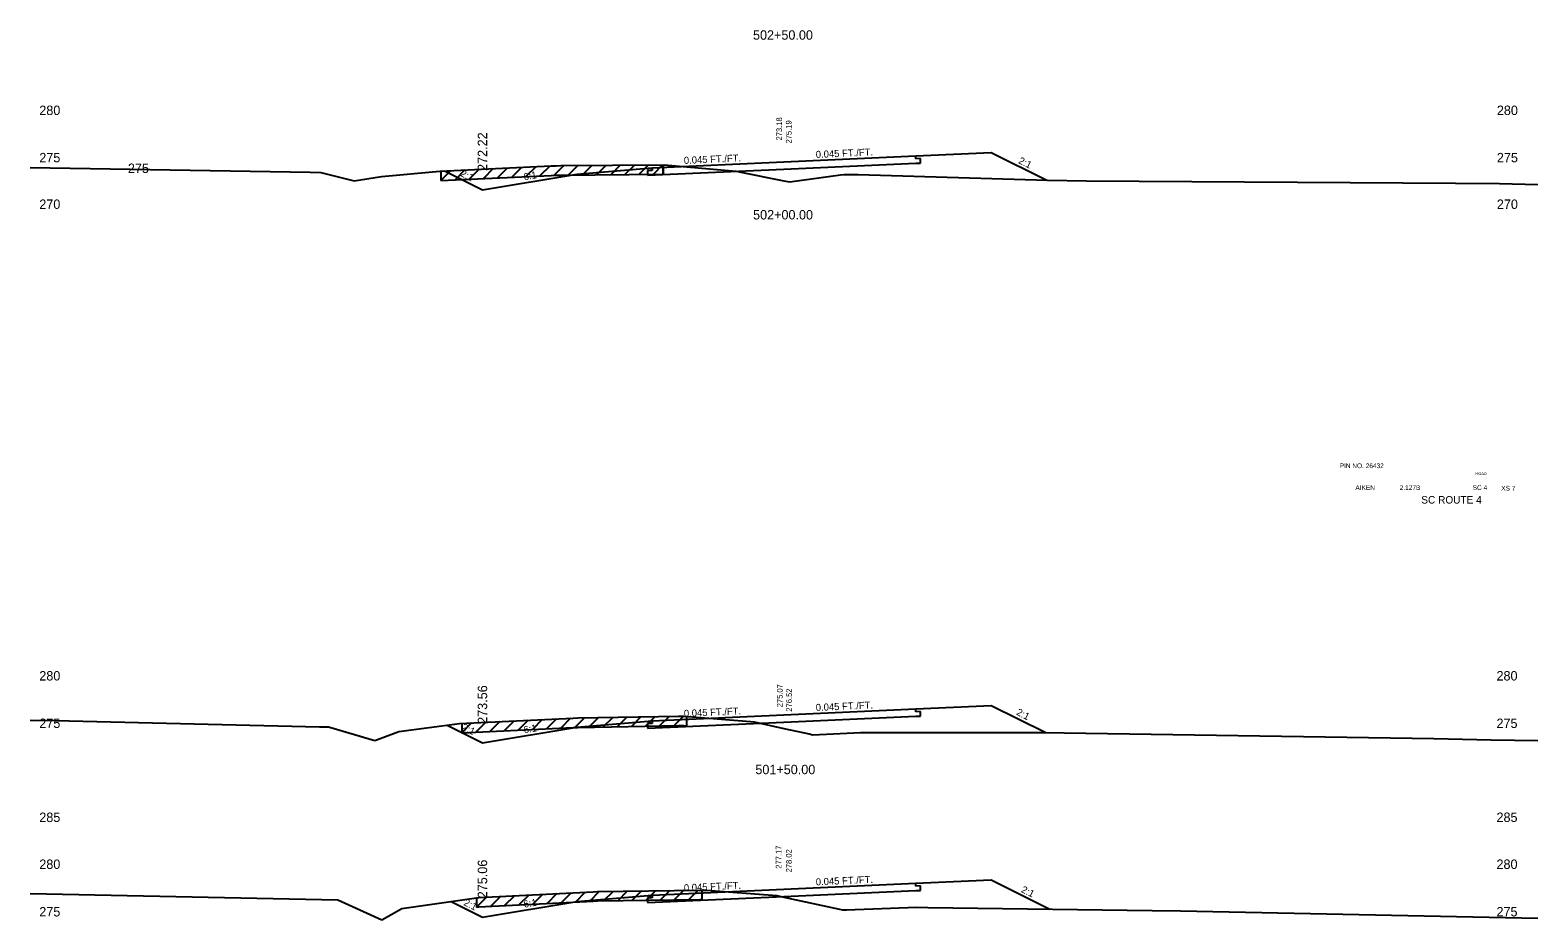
# Model space of a CAD drawing. Extents: x 883 to 1160, y 1002 to 4323.
# Drawn here: x 1000 to 1160, y 1744.8 to 1839.2 of the extents above; entities that cross this region are included whole.
import ezdxf

# ---------------------------------------------------------------- set-up
doc = ezdxf.new("R2010")
doc.units = 0
for name, color, linetype in [('Level 1', 7, 'Continuous'), ('Level 10', 7, 'Continuous'), ('Level 11', 7, 'Continuous'), ('Level 12', 7, 'Continuous'), ('Level 3', 7, 'Continuous'), ('Level 32', 7, 'Continuous'), ('Level 33', 7, 'Continuous'), ('Level 59', 7, 'Continuous'), ('Level 6', 7, 'Continuous'), ('Level 60', 7, 'Continuous'), ('Level 61', 7, 'Continuous'), ('Level 7', 7, 'Continuous')]:
    doc.layers.add(name, color=color, linetype=linetype)

msp = doc.modelspace()

# ---------------------------------------------------------------- linework, layer by layer
at = {"layer": 'Level 11'}
for p, q in [((1094, 1825.52), (1094, 1825.82)), ((1094.5, 1825.54), (1094, 1825.52)), ((1094, 1825.04), (1094.5, 1825.06)), ((1094.5, 1825.06), (1094.5, 1825.54)), ((1094, 1766.85), (1094, 1767.15)), ((1094.5, 1766.87), (1094, 1766.85)), ((1094.5, 1766.39), (1094.5, 1766.87)), ((1094, 1766.37), (1094.5, 1766.39)), ((1094, 1748.35), (1094, 1748.65)), ((1094.5, 1748.37), (1094, 1748.35)), ((1094, 1747.87), (1094.5, 1747.89)), ((1094.5, 1747.89), (1094.5, 1748.37))]:
    msp.add_line(p, q, dxfattribs=at)
at = {"layer": 'Level 12'}
for p, q in [((1065.5, 1823.78), (1080, 1824.41)), ((1066, 1824.26), (1065.5, 1824.26)), ((1065.5, 1824.26), (1065.5, 1823.78)), ((1066, 1824.56), (1066, 1824.26)), ((1067.19, 1824.86), (1067.19, 1823.83)), ((1080, 1824.41), (1094, 1825.04)), ((1065.5, 1765.11), (1080, 1765.74)), ((1066, 1765.59), (1065.5, 1765.59)), ((1065.5, 1765.59), (1065.5, 1765.11)), ((1066, 1765.89), (1066, 1765.59)), ((1080, 1765.74), (1094, 1766.37)), ((1065.5, 1746.61), (1080, 1747.24)), ((1066, 1747.39), (1066, 1747.09)), ((1080, 1747.24), (1094, 1747.87)), ((1066, 1747.09), (1065.5, 1747.09)), ((1065.5, 1747.09), (1065.5, 1746.61))]:
    msp.add_line(p, q, dxfattribs=at)
at = {"layer": 'Level 59'}
for p, q in [((1080, 1825.19), (1094, 1825.82)), ((1066, 1824.56), (1080, 1825.19)), ((1066, 1765.89), (1080, 1766.52)), ((1080, 1766.52), (1094, 1767.15)), ((1066, 1747.39), (1080, 1748.02)), ((1080, 1748.02), (1094, 1748.65))]:
    msp.add_line(p, q, dxfattribs=at)
at = {"layer": 'Level 6'}
for p, q in [((1094, 1825.82), (1102, 1826.18)), ((1058, 1823.89), (1066, 1824.56)), ((1094, 1767.15), (1102, 1767.51)), ((1058, 1765.22), (1066, 1765.89)), ((1094, 1748.65), (1102, 1749.01)), ((1058, 1746.72), (1066, 1747.39))]:
    msp.add_line(p, q, dxfattribs=at)
at = {"layer": 'Level 60'}
for p, q in [((1000, 1824.59), (1004.24, 1824.52)), ((1004.24, 1824.52), (1029.72, 1824.1)), ((1029.72, 1824.1), (1030.86, 1824.06)), ((1030.86, 1824.06), (1034.39, 1823.17)), ((1037.28, 1823.64), (1043.49, 1824.21)), ((1043.49, 1824.21), (1055.3, 1824.75)), ((1055.3, 1824.75), (1055.83, 1824.77)), ((1055.83, 1824.77), (1056.31, 1824.78)), ((1056.31, 1824.78), (1067.27, 1824.86)), ((1067.27, 1824.86), (1074.49, 1824.24)), ((1074.49, 1824.24), (1074.91, 1824.21)), ((1074.91, 1824.21), (1075.25, 1824.13)), ((1075.25, 1824.13), (1080, 1823.18)), ((1034.39, 1823.17), (1037.28, 1823.64)), ((1080, 1823.18), (1080.63, 1823.05)), ((1080.63, 1823.05), (1086, 1823.82)), ((1086, 1823.82), (1086.38, 1823.84)), ((1086.38, 1823.84), (1087.87, 1823.83)), ((1087.87, 1823.83), (1107.95, 1823.23)), ((1107.95, 1823.23), (1112.09, 1823.17)), ((1112.09, 1823.17), (1151.26, 1822.93)), ((1151.26, 1822.93), (1155.94, 1822.87)), ((1155.94, 1822.87), (1160, 1822.79)), ((1000, 1765.97), (1002.64, 1765.91)), ((1002.64, 1765.91), (1030.7, 1765.26)), ((1030.7, 1765.26), (1031.67, 1765.24)), ((1031.67, 1765.24), (1036.58, 1763.79)), ((1039.13, 1764.75), (1045.58, 1765.61)), ((1045.58, 1765.61), (1057.64, 1766.17)), ((1057.64, 1766.17), (1058.11, 1766.19)), ((1058.11, 1766.19), (1068.82, 1766.37)), ((1068.82, 1766.37), (1069.37, 1766.38)), ((1069.37, 1766.38), (1076.44, 1765.8)), ((1076.44, 1765.8), (1076.84, 1765.77)), ((1076.84, 1765.77), (1080, 1765.07)), ((1080, 1765.07), (1082.66, 1764.49)), ((1036.58, 1763.79), (1039.13, 1764.75)), ((1082.66, 1764.49), (1083.05, 1764.4)), ((1083.05, 1764.4), (1088.12, 1764.63)), ((1088.12, 1764.63), (1088.57, 1764.64)), ((1088.57, 1764.64), (1107.64, 1764.63)), ((1107.64, 1764.63), (1109.73, 1764.6)), ((1109.73, 1764.6), (1148.97, 1763.99)), ((1148.97, 1763.99), (1155.04, 1763.86)), ((1155.04, 1763.86), (1160, 1763.79)), ((1000, 1747.57), (1032.64, 1746.89)), ((1047.61, 1747.14), (1059.75, 1747.75)), ((1059.75, 1747.75), (1060.2, 1747.77)), ((1060.2, 1747.77), (1071.08, 1747.92)), ((1071.08, 1747.92), (1071.78, 1747.9)), ((1071.78, 1747.9), (1079.25, 1747.34)), ((1079.25, 1747.34), (1080, 1747.17)), ((1032.64, 1746.89), (1037.32, 1744.77)), ((1037.32, 1744.77), (1039.46, 1745.97)), ((1039.46, 1745.97), (1047.61, 1747.14)), ((1080, 1747.17), (1085.9, 1745.9)), ((1085.9, 1745.9), (1086.21, 1745.82)), ((1086.21, 1745.82), (1086.64, 1745.82)), ((1086.64, 1745.82), (1094.11, 1746.1)), ((1094.11, 1746.1), (1095.27, 1746.08)), ((1095.27, 1746.08), (1119.07, 1745.76)), ((1119.07, 1745.76), (1122.07, 1745.71)), ((1122.07, 1745.71), (1160, 1744.94))]:
    msp.add_line(p, q, dxfattribs=at)
at = {"layer": 'Level 61'}
for p, q in [((1044.64, 1824.26), (1043.59, 1823.22)), ((1043.59, 1824.22), (1043.59, 1823.22)), ((1046.14, 1824.33), (1045.09, 1823.29)), ((1047.64, 1824.4), (1046.6, 1823.35)), ((1049.14, 1824.47), (1048.1, 1823.42)), ((1050.65, 1824.54), (1049.6, 1823.49)), ((1052.15, 1824.6), (1051.1, 1823.56)), ((1053.65, 1824.67), (1052.6, 1823.62)), ((1055.15, 1824.74), (1054.1, 1823.69)), ((1056.62, 1824.78), (1055.6, 1823.76)), ((1058.11, 1824.79), (1057.1, 1823.78)), ((1059.61, 1824.8), (1058.6, 1823.8)), ((1061.11, 1824.81), (1060.1, 1823.81)), ((1062.61, 1824.83), (1061.61, 1823.82)), ((1064.12, 1824.84), (1063.11, 1823.83)), ((1065.62, 1824.85), (1064.61, 1823.84)), ((1067.12, 1824.86), (1066.11, 1823.85)), ((1067.19, 1823.86), (1067.19, 1824.86)), ((1043.59, 1823.22), (1055.3, 1823.75)), ((1055.3, 1823.75), (1055.83, 1823.77)), ((1055.83, 1823.77), (1056.31, 1823.78)), ((1056.31, 1823.78), (1067.19, 1823.86)), ((1046.85, 1765.66), (1045.8, 1764.62)), ((1045.8, 1765.62), (1045.8, 1764.62)), ((1045.8, 1764.62), (1057.64, 1765.17)), ((1048.35, 1765.73), (1047.3, 1764.69)), ((1049.85, 1765.8), (1048.8, 1764.76)), ((1051.35, 1765.87), (1050.3, 1764.83)), ((1052.85, 1765.94), (1051.8, 1764.89)), ((1054.35, 1766.01), (1053.3, 1764.96)), ((1055.85, 1766.08), (1054.8, 1765.03)), ((1057.35, 1766.15), (1056.3, 1765.1)), ((1057.64, 1765.17), (1058.11, 1765.19)), ((1058.83, 1766.2), (1057.8, 1765.17)), ((1058.11, 1765.19), (1068.82, 1765.37)), ((1060.32, 1766.23), (1059.3, 1765.21)), ((1061.82, 1766.25), (1060.8, 1765.23)), ((1063.32, 1766.28), (1062.3, 1765.26)), ((1064.82, 1766.3), (1063.8, 1765.29)), ((1066.32, 1766.33), (1065.3, 1765.31)), ((1067.82, 1766.35), (1066.8, 1765.34)), ((1069.32, 1766.38), (1068.31, 1765.36)), ((1068.82, 1765.37), (1069.37, 1765.38)), ((1069.37, 1765.38), (1069.7, 1765.35)), ((1069.7, 1765.35), (1069.7, 1766.35)), ((1049.9, 1747.25), (1048.85, 1746.2)), ((1051.4, 1747.33), (1050.35, 1746.28)), ((1052.91, 1747.4), (1051.85, 1746.35)), ((1054.41, 1747.48), (1053.35, 1746.43)), ((1055.91, 1747.56), (1054.85, 1746.5)), ((1057.41, 1747.63), (1056.35, 1746.58)), ((1058.91, 1747.71), (1057.86, 1746.65)), ((1060.4, 1747.77), (1059.36, 1746.73)), ((1061.87, 1747.79), (1060.86, 1746.78)), ((1063.37, 1747.81), (1062.36, 1746.8)), ((1064.87, 1747.84), (1063.86, 1746.82)), ((1066.38, 1747.86), (1065.36, 1746.84)), ((1067.88, 1747.88), (1066.86, 1746.86)), ((1069.38, 1747.9), (1068.36, 1746.88)), ((1070.88, 1747.92), (1069.86, 1746.9)), ((1071.32, 1746.91), (1071.32, 1747.91)), ((1048.43, 1747.18), (1047.35, 1746.1)), ((1047.35, 1747.1), (1047.35, 1746.1)), ((1047.35, 1746.1), (1047.61, 1746.14)), ((1047.61, 1746.14), (1059.75, 1746.75)), ((1059.75, 1746.75), (1060.2, 1746.77)), ((1060.2, 1746.77), (1071.08, 1746.92)), ((1071.08, 1746.92), (1071.32, 1746.91))]:
    msp.add_line(p, q, dxfattribs=at)
at = {"layer": 'Level 7'}
for p, q in [((1102, 1826.18), (1107.88, 1823.24)), ((1043.98, 1824.23), (1048, 1822.22)), ((1048, 1822.22), (1058, 1823.89)), ((1102, 1767.51), (1107.77, 1764.63)), ((1044.26, 1765.43), (1048, 1763.56)), ((1048, 1763.56), (1058, 1765.22)), ((1102, 1749.01), (1108.21, 1745.9)), ((1044.68, 1746.72), (1048, 1745.06)), ((1048, 1745.06), (1058, 1746.72))]:
    msp.add_line(p, q, dxfattribs=at)

# ---------------------------------------------------------------- texts
at = {"layer": 'Level 1'}
for s, height, p in [('502+50.00', 1, (1076.71, 1838.14)), ('502+00.00', 1, (1076.72, 1819.07)), ('PIN NO. 26432', 0.5, (1138.97, 1792.69)), ('AIKEN', 0.5, (1140.64, 1790.37)), (' 2.127B', 0.5, (1145.15, 1790.37)), ('SC 4', 0.5, (1153.09, 1790.37)), ('XS 7', 0.5, (1156.12, 1790.31)), ('SC ROUTE 4', 0.8, (1147.63, 1788.93)), ('501+50.00', 1, (1076.96, 1760.22))]:
    msp.add_text(s, height=height, dxfattribs=at).set_placement(p)
at = {"layer": 'Level 10'}
for s, p in [('273.18', (1079.79, 1827.45)), ('275.07', (1079.85, 1767.32)), ('277.17', (1079.73, 1750.19))]:
    msp.add_text(s, height=0.6, rotation=90, dxfattribs=at).set_placement(p)
at = {"layer": 'Level 3'}
for s, height, p in [(' 280', 1, (1000.6, 1830.15)), (' 280', 1, (1155.28, 1830.15)), (' 275', 1, (1000.6, 1825.13)), (' 275', 1, (1155.28, 1825.13)), (' 275', 1, (1010, 1824)), (' 270', 1, (1000.6, 1820.19)), (' 270', 1, (1155.28, 1820.19)), ('ROAD', 0.3, (1153.38, 1791.96)), (' 280', 1, (1000.6, 1770.16)), (' 280', 1, (1155.24, 1770.16)), (' 275', 1, (1000.6, 1765.12)), (' 275', 1, (1155.24, 1765.12)), (' 285', 1, (1000.6, 1755.15)), (' 285', 1, (1155.24, 1755.15)), (' 280', 1, (1000.6, 1750.17)), (' 280', 1, (1155.24, 1750.17)), (' 275', 1, (1000.6, 1745.13)), (' 275', 1, (1155.24, 1745.13))]:
    msp.add_text(s, height=height, dxfattribs=at).set_placement(p)
at = {"layer": 'Level 32'}
for s, rotation, p in [('0.045 FT./FT.', 2.5766, (1069.39, 1824.96)), ('0.045 FT./FT.', 2.5766, (1083.39, 1825.59)), ('2:1', 333.435, (1104.81, 1825.07)), ('2:1', 333.435, (1045.59, 1823.71)), ('6:1', 9.4623, (1052.43, 1823.22)), ('0.045 FT./FT.', 2.5766, (1069.39, 1766.29)), ('0.045 FT./FT.', 2.5766, (1083.39, 1766.92)), ('2:1', 333.435, (1104.59, 1766.56)), ('2:1', 333.435, (1045.73, 1764.97)), ('6:1', 9.4623, (1052.43, 1764.55)), ('0.045 FT./FT.', 2.5766, (1069.39, 1747.79)), ('0.045 FT./FT.', 2.5766, (1083.39, 1748.42)), ('2:1', 333.435, (1105.1, 1747.74)), ('2:1', 333.435, (1045.94, 1746.36)), ('6:1', 9.4623, (1052.43, 1746.05))]:
    msp.add_text(s, height=0.75, rotation=rotation, dxfattribs=at).set_placement(p)
at = {"layer": 'Level 33'}
for s, p in [('272.22', (1048.5, 1824.22)), ('273.56', (1048.5, 1765.56)), ('275.06', (1048.5, 1747.06))]:
    msp.add_text(s, height=1, rotation=90, dxfattribs=at).set_placement(p)
at = {"layer": 'Level 59'}
for s, p in [(' 275.19', (1080.8, 1826.91)), (' 276.52', (1080.84, 1766.63)), (' 278.02', (1080.82, 1749.58))]:
    msp.add_text(s, height=0.6, rotation=90, dxfattribs=at).set_placement(p)

doc.saveas('drawing.dxf')
